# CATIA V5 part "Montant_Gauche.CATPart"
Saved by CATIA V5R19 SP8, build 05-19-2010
Part number: Montant_Gauche
Nomenclature: 2
Material "Acier": density 7860 kg/m3, Young's modulus 2e+11 Pa, Poisson ratio 0.266, thermal expansion 1.17e-05 1/K
Bounding box of the stored display mesh (mm): x -22.481 to 80.5, y -67.011 to 64.472, z 0 to 1194.396
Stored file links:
  C:\Users\rphgr\Desktop\0_Tapis_TC520B_vitesse\Montant_Gauche.CATPart
  D:\Programmes\DassaultSysteme\win_b64\reffiles\standard\MetricThickPitch.txt
  D:\Programmes\DassaultSysteme\win_b64\startup\materials\French\Catalog.CATMaterial
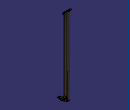
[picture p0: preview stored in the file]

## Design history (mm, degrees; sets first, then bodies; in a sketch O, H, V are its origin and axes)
AxisSystem1: origin (0, 0, 0), X (1, 0, 0), Y (0, 1, 0), Z (0, 0, 1)
Body1 (main body), material "Acier"
  Sketch1 on XY plane of AxisSystem1, origin (0, 0, 0), H (1, 0, 0), V (0, 1, 0)
    construction line L1 (0, 20) -> (0, -20)
    point P1 (0, 20)
    point P2 (0, -20)
    line L2 (20, 20) -> (20, -20)
    line L3 (-20, -20) -> (-20, 20)
    arc A1 centre (0, -20) radius 20 from (20, -20) to (-20, -20) cw
    arc A2 centre (0, 20) radius 20 from (-20, 20) to (20, 20) cw
    distance L1 L2 = 20
    length L1 = 40
    distance P2 O = 20
    coincidence: P1 V
    vertical: L1 V
    tangency: A1 L2, A2 L2, A1 L3, A2 L3
  Pad1: profile Sketch1, direction (0, 0, 1), length 1220, thin wall 1.5
  Sketch2 on YZ plane of AxisSystem1, origin (0, 0, 0), H (0, 1, 0), V (0, 0, 1)
    line L1 (-40, 1110) -> (-40, 0)
    point P2 (-40, 0)
    line L2 (-40, 0) -> (40, 21.4359)
    line L3 (40, 21.4359) -> (40, 1190)
    line L4 (40, 1190) -> (-40, 1110)
    reference intersected line E1 through (0, 0) direction (-1, 0) from XY plane of AxisSystem1
    distance P2 O = 40
    distance L1 L3 = 80
    angle L1 L2 = 75
    length L1 = 1110
    angle L4 L3 = 45
    vertical: L1 V
    coincidence: P2 E1
  Pocket1: profile Sketch2, direction (-1, 0, 0), through (limit type 3), opposite side through (limit type 3), outer side
  Sketch3 on face of Pad1, origin (18.5, 0, 0), H (0, -1, 0), V (0, 0, 1)
    line L1 (-17, 61.6004) -> (17, 61.6004)
    line L2 (20, 58.6004) -> (20, 24.6004)
    line L3 (17, 21.6004) -> (-17, 21.6004)
    line L4 (-20, 24.6004) -> (-20, 58.6004)
    arc A1 centre (-17, 58.6004) radius 3 from (-17, 61.6004) to (-20, 58.6004) ccw
    arc A2 centre (17, 58.6004) radius 3 from (17, 61.6004) to (20, 58.6004) cw
    arc A3 centre (17, 24.6004) radius 3 from (20, 24.6004) to (17, 21.6004) cw
    arc A4 centre (-17, 24.6004) radius 3 from (-17, 21.6004) to (-20, 24.6004) cw
    distance L2 L4 = 40
    distance L3 L1 = 40
    radius A1 = 3
    radius A2 = 3
    radius A3 = 3
    radius A4 = 3
    distance L4 V = 20
    horizontal: L1 H, L3 H
    vertical: L2 V, L4 V
    tangency: A1 L1, A1 L4, A2 L1, A2 L2, A3 L2, A3 L3, A4 L3, A4 L4
  Pad2: profile Sketch3, direction (-1, 0, 0), length 67, thin wall 1.5
  Sketch4 on face of Pad1, origin (-20, 0, 0), H (0, -1, 0), V (0, 0, 1)
  Pocket2: profile Sketch4, direction (1, 0, 0), through (limit type 6)
  Sketch5 on face of Pad2, origin (0, 0, 21.6004), H (1, 0, 0), V (0, -1, 0)
    construction line L1 (-4, 0) -> (4, 0)
    point P2 (4, 0)
    line L2 (-4, 8) -> (4, 8)
    line L3 (4, -8) -> (-4, -8)
    arc A1 centre (4, 0) radius 8 from (4, 8) to (4, -8) cw
    arc A2 centre (-4, 0) radius 8 from (-4, -8) to (-4, 8) cw
    reference intersected line E1 through (0, 0) direction (0, 1) from YZ plane of AxisSystem1
    distance L1 L2 = 8
    length L1 = 8
    distance P2 E1 = 4
    horizontal: L1 H
    tangency: A1 L2, A2 L2, A1 L3, A2 L3
    coincidence: L1 H
  Pocket3: profile Sketch5, direction (0, 0, 1), through (limit type 3)
  Plane1: type Angle, RefPlane face of Pocket1 from Sketch2.L2, Direction edge [XY plane of AxisSystem1 | ZX plane of AxisSystem1], Angle 90
  Sketch6 on Plane1, origin (0, 0, 0), H (1, 0, 0), V (0, -0.2588, 0.9659)
    point P1 (-80.5, 65.3528)
    line L1 (-80.5, 65.3528) -> (-54.5, 65.3528)
    arc A1 centre (-54.5, 59.3528) radius 6 from (-54.5, 65.3528) to (-48.5, 59.3528) cw
    line L2 (-48.5, 59.3528) -> (-48.5, 20.3528)
    point P5 (-48.5, 20.3528)
    reference intersected line E1 through (-48.5, 0) direction (0, -1) from end face of Pad2
    reference intersected line E2 through (0, 10.3528) direction (-1, 0) from face of Pocket1 from Sketch2.L2
    angle L1 L2 = 90
    distance P5 L1 = 45
    distance P1 L2 = 32
    radius A1 = 6
    distance P5 E2 = 10
    tangency: A1 L1, L2 A1
    coincidence: L2 E1
  Pad3: profile Sketch6, direction (0, -0.9659, -0.2588), length 51.864, opposite side length 73.136, thin wall 4
  Fillet1: radius 4, on edge [face of Pad3 | end face of Pad3] (x2); edge [start face of Pad3 | face of Pad3] (x2)
  Sketch7 on face of Pad3, origin (-52.5, 0, 0), H (0, -1, 0), V (0, 0, 1)
    construction line L1 (47.6556, 23.8306) -> (46.8792, 20.9328)
    point P2 (46.8792, 20.9328)
    line L2 (52.0023, 22.6659) -> (51.2258, 19.7681)
    line L3 (42.5325, 22.0975) -> (43.309, 24.9953)
    arc A1 centre (46.8792, 20.9328) radius 4.5 from (51.2258, 19.7681) to (42.5325, 22.0975) cw
    arc A2 centre (47.6556, 23.8306) radius 4.5 from (43.309, 24.9953) to (52.0023, 22.6659) cw
    construction line L4 (-48.9369, 49.7125) -> (-49.7134, 46.8147)
    point P8 (-49.7134, 46.8147)
    line L5 (-44.5903, 48.5478) -> (-45.3667, 45.65)
    line L6 (-54.0601, 47.9794) -> (-53.2836, 50.8772)
    arc A3 centre (-49.7134, 46.8147) radius 4.5 from (-45.3667, 45.65) to (-54.0601, 47.9794) cw
    arc A4 centre (-48.9369, 49.7125) radius 4.5 from (-53.2836, 50.8772) to (-44.5903, 48.5478) cw
    reference intersected line E1 (66.9225, 49.3711) -> (55.3645, 6.2359) from end face of Pad3
    reference intersected line E2 (65.638, 3.4831) -> (-55.1027, 35.8354) from face of Pad3
    reference intersected line E3 (65.638, 3.4831) -> (-55.1027, 35.8354) from face of Pad3
    construction line L7 (-4.6593, 43.0247) -> (5, 40.4365)
    point P14 (5, 40.4365)
    line L8 (-2.0711, 52.684) -> (7.5882, 50.0958)
    line L9 (2.4118, 30.7772) -> (-7.2474, 33.3654)
    arc A5 centre (5, 40.4365) radius 10 from (7.5882, 50.0958) to (2.4118, 30.7772) cw
    arc A6 centre (-4.6593, 43.0247) radius 10 from (-7.2474, 33.3654) to (-2.0711, 52.684) cw
    reference intersected line E4 (65.638, 3.4831) -> (-55.1027, 35.8354) from face of Pad3
    distance L1 L2 = 4.5
    distance L4 L5 = 4.5
    length L1 = 3
    length L4 = 3
    distance L4 L1 = 100
    distance L1 E1 = 12
    distance P2 E2 = 12
    distance P8 E3 = 12
    distance L7 L8 = 10
    distance L7 E4 = 20
    length L7 = 10
    distance P14 V = 5
    tangency: A1 L2, A2 L2, A1 L3, A2 L3, A3 L5, A4 L5, A3 L6, A4 L6, A5 L8, A6 L8, A5 L9, A6 L9
    perpendicularity: L7 L3
  Pocket4: profile Sketch7, direction (1, 0, 0), through (limit type 6)
  Sketch8 on face of Pad3, origin (0, -15.8793, 59.2622), H (-1, 0, 0), V (0, 0.9659, 0.2588)
    construction line L1 (66.8047, 54.136) -> (66.8047, 52.136)
    point P1 (66.8047, 54.136)
    line L2 (71.3047, 54.136) -> (71.3047, 52.136)
    line L3 (62.3047, 52.136) -> (62.3047, 54.136)
    arc A1 centre (66.8047, 52.136) radius 4.5 from (71.3047, 52.136) to (62.3047, 52.136) cw
    arc A2 centre (66.8047, 54.136) radius 4.5 from (62.3047, 54.136) to (71.3047, 54.136) cw
    construction line L4 (66.8047, -30.864) -> (66.8047, -32.864)
    point P7 (66.8047, -30.864)
    point P8 (66.8047, -32.864)
    line L5 (71.3047, -30.864) -> (71.3047, -32.864)
    line L6 (62.3047, -32.864) -> (62.3047, -30.864)
    arc A3 centre (66.8047, -32.864) radius 4.5 from (71.3047, -32.864) to (62.3047, -32.864) cw
    arc A4 centre (66.8047, -30.864) radius 4.5 from (62.3047, -30.864) to (71.3047, -30.864) cw
    reference intersected line E1 (80.5, 73.136) -> (80.5, -51.864) from face of Pad3
    reference intersected line E2 (80.5, -51.864) -> (48.8431, -51.864) from end face of Pad3
    reference projected line E3 (80.5, 73.136) -> (54.5, 73.136) from edge [face of Pad3 | start face of Pad3]
    distance L1 L2 = 4.5
    distance L4 L5 = 4.5
    distance L1 E1 = 13.6953
    length L1 = 2
    length L4 = 2
    distance P8 E2 = 19
    distance P1 E3 = 19
    vertical: L1 V, L4 V
    tangency: A1 L2, A2 L2, A1 L3, A2 L3, A3 L5, A4 L5, A3 L6, A4 L6
    coincidence: P7 L1
  Pocket5: profile Sketch8, direction (0, -0.2588, 0.9659), through (limit type 6)
  Plane2: type Normal, Curve edge [face of Pocket1 from Sketch2.L4 | face of Pad1], RefPoint vertex [face of Pad1 | face of Pocket1 from Sketch2.L4 | face of Pad1]
  Plane3: type Offset, RefPlane face of Pocket1 from Sketch2.L4, Offset 0, reversed
  Sketch9 on Plane2, origin (0, 555, 555), H (-1, 0, 0), V (0, -0.7071, 0.7071)
    arc A1 centre (0, 824.5306) radius 23 from (-22.5834, 820.1728) to (22.5834, 820.1728) ccw
    point P1 (0, 824.5306)
    reference projected point E1 (-20, 813.1728) from edge [face of Pocket1 from Sketch2.L4 | face of Pad1]
    axis line L1 (-28.642, 820.1728) -> (24.6976, 820.1728)
    reference intersected line E2 through (0, 813.1728) direction (1, 0) from face of Pocket1 from Sketch2.L4
    point P4 (22.5834, 820.1728)
    point P5 (-22.5834, 820.1728)
    radius A1 = 23
    distance L1 E2 = 7
    coincidence: P1 V, A1 E1, L1 P4, L1 P5
    horizontal: L1 H
  Pad4: profile Sketch9, direction (0, -0.7071, -0.7071), length 41, opposite side length 95, thin wall 3
  Sketch10 on Plane2, origin (0, 555, 555), H (-1, 0, 0), V (0, -0.7071, 0.7071)
    projected arc E1 centre (0, 824.5306) radius 20 from (-19.6377, 820.7412) to (19.6377, 820.7412) ccw from edge [start face of Pad4 | face of Pad4]
  Pocket6: profile Sketch10, direction (0, 0.7071, 0.7071), length 91, opposite side length 71
  Fillet2: radius 20, on edge [face of Pad4 | start face of Pad4] (x2); edge [end face of Pad4 | face of Pad4] (x2)
  Fillet3: radius 0.5, on face of Pad4
  Sketch11 on Plane3, origin (0, -575, 575), H (-1, 0, 0), V (0, 0.7071, 0.7071)
    construction line L1 (0, 818.1728) -> (0, 808.1728)
    point P1 (0, 818.1728)
    line L2 (10, 818.1728) -> (10, 808.1728)
    line L3 (-10, 808.1728) -> (-10, 818.1728)
    arc A1 centre (0, 808.1728) radius 10 from (10, 808.1728) to (-10, 808.1728) cw
    arc A2 centre (0, 818.1728) radius 10 from (-10, 818.1728) to (10, 818.1728) cw
    reference intersected line E1 through (0, 0) direction (0, -1) from YZ plane of AxisSystem1
    reference intersected line E2 through (0, 813.1728) direction (-1, 0) from ZX plane of AxisSystem1
    distance L1 L2 = 10
    length L1 = 10
    distance P1 E2 = 5
    vertical: L1 V
    tangency: A1 L2, A2 L2, A1 L3, A2 L3
    coincidence: L1 E1
  Pocket7: profile Sketch11, direction (0, -0.7071, 0.7071), length 22, mirrored extent
  Sketch12 on Plane3, origin (5.7218, 33.2205, 1183.2205), H (1, 0, 0), V (0, -0.7071, -0.7071)
    point P1 (-5.7218, 16.9808)
    reference intersected line E1 through (-5.7218, 0) direction (0, 1) from YZ plane of AxisSystem1
    reference projected point E2 (-5.7218, 41.9808) from axis of face of Pocket7 from Sketch11.A2
    distance P1 E2 = 25
    coincidence: P1 E1
  Hole1: placed by Sketch12, at (0, 21.2132, 1171.2132) direction (0, -0.7071, 0.7071), diameter 6.647, through (limit type 6), threaded "M8", thread diameter 8, thread depth -8.3449, pitch 1.25
  Sketch13 on Plane3, origin (1.2244, 36.2824, 1186.2824), H (1, 0, 0), V (0, -0.7071, -0.7071)
    point P1 (-1.2244, 81.311)
    reference intersected line E1 through (-1.2244, 0) direction (0, 1) from YZ plane of AxisSystem1
    reference projected point E2 (-1.2244, 56.311) from axis of face of Pocket7 from Sketch11.A1
    distance E2 P1 = 25
    coincidence: P1 E1
  Hole2: placed by Sketch13, at (0, -21.2132, 1128.7868) direction (0, -0.7071, 0.7071), diameter 6.647, through (limit type 6), threaded "M8", thread diameter 8, thread depth -8.3449, pitch 1.25
  Symmetry1: ToTransfor Hole2, Reference yz-plane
